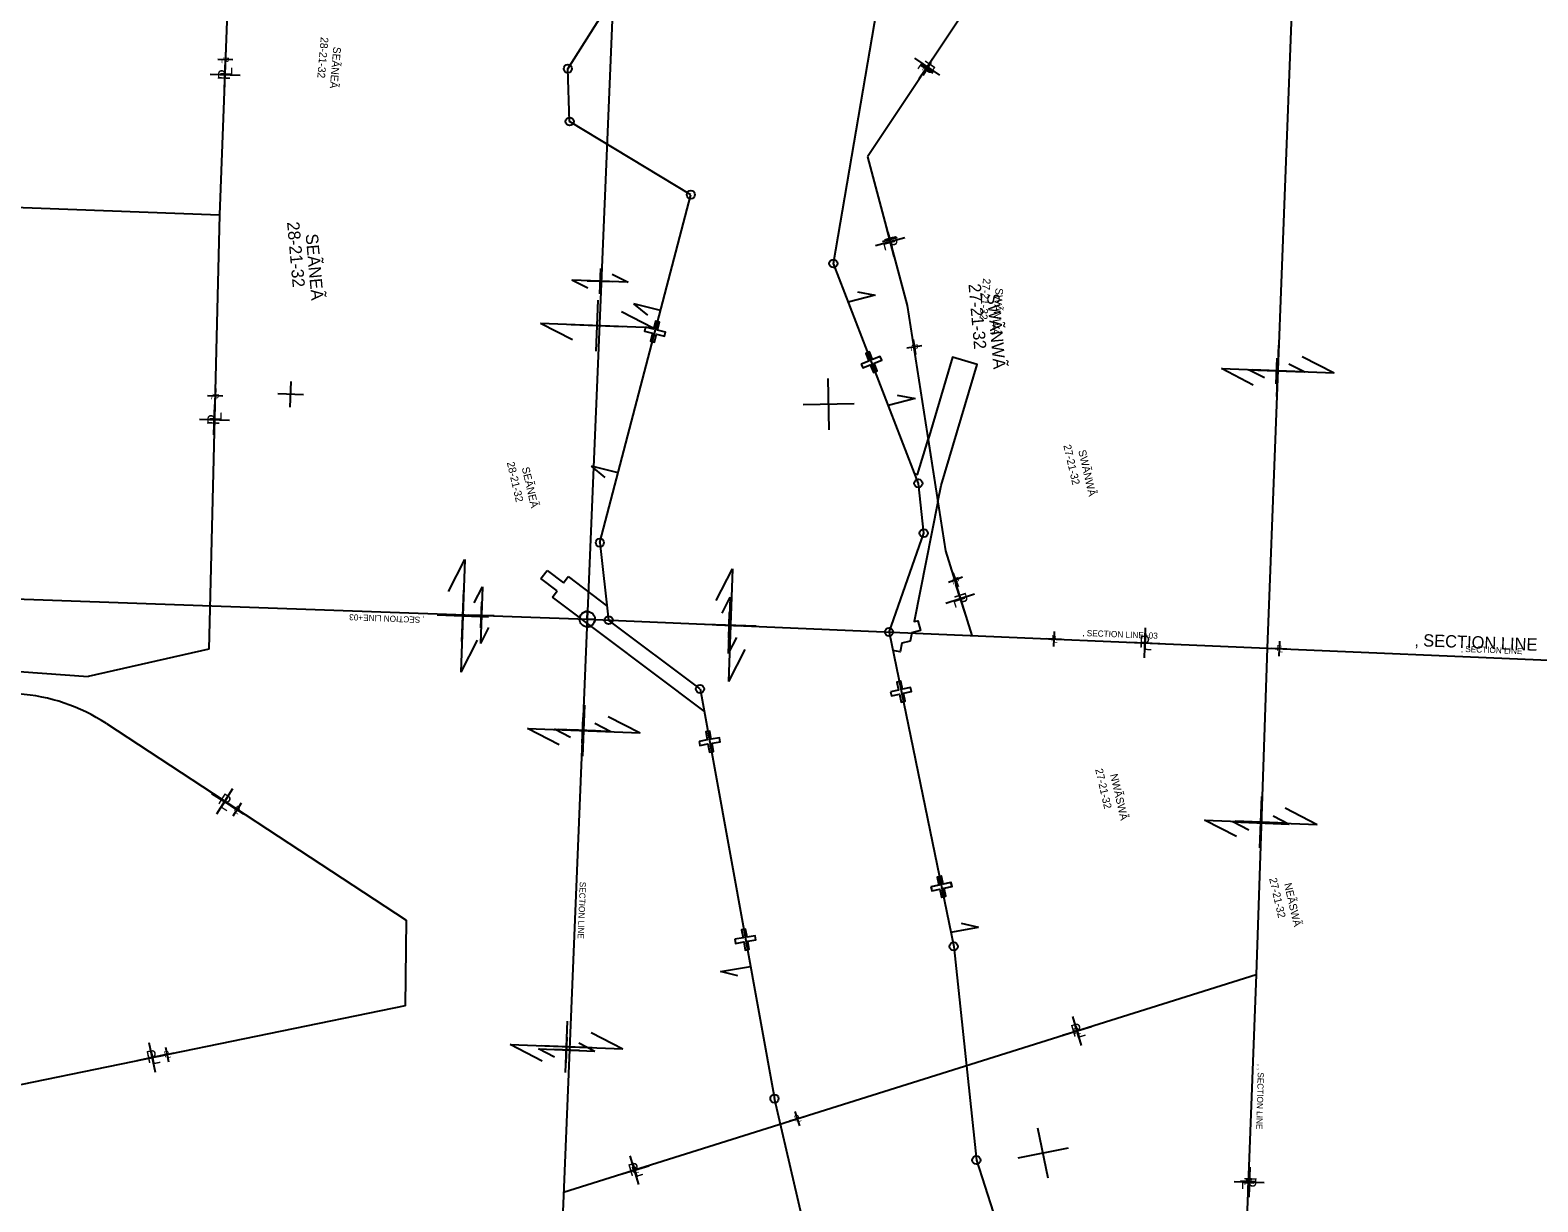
# Model space of a CAD drawing. Extents: x 2814293 to 2835768, y 121185 to 156337.
# Drawn here: x 2819450 to 2822390, y 127276 to 129561 of the extents above; entities that cross this region are included whole.
import ezdxf

# ---------------------------------------------------------------- set-up
doc = ezdxf.new("R2010")
doc.units = 0
for name, color, linetype in [('Default', 7, 'Continuous'), ('Photo-Retaining wall', 7, 'Continuous'), ('Roadway-Alignment notes', 7, 'Continuous'), ('Roadway-Edge of pavement', 7, 'Continuous'), ('Roadway-Edge of shoulder', 7, 'Continuous'), ('Roadway-Entrances', 7, 'Continuous'), ('Roadway-New rw', 7, 'Continuous'), ('Roadway-Permanent easement', 7, 'Continuous'), ('Roadway-Safety', 7, 'Continuous'), ('Roadway-Walls', 7, 'Continuous'), ('Scratch-2', 7, 'Continuous'), ('Scratch-4', 7, 'Continuous'), ('Scratch-5', 7, 'Continuous'), ('Text-New rw label', 7, 'Continuous'), ('Traffic_Control-Traffic barriers', 7, 'Continuous')]:
    doc.layers.add(name, color=color, linetype=linetype)

msp = doc.modelspace()

# ---------------------------------------------------------------- linework, layer by layer
at = {"layer": 'Default'}
for p, q in [((2819957, 128826.3), (2819959, 128876.2)), ((2821008.3, 128781.6), (2821005.9, 128881.6)), ((2819983, 128850.3), (2819933, 128852.2)), ((2821057.1, 128832.8), (2820957.1, 128830.4)), ((2821435, 127321.8), (2821414.9, 127419.8)), ((2821473.9, 127380.8), (2821376, 127360.8))]:
    msp.add_line(p, q, dxfattribs=at)
at = {"layer": 'Roadway-Edge of pavement'}
for p, q in [((2820562, 129096.8), (2820560.1, 129046.8)), ((2820616, 129069.7), (2820506.1, 129073.9)), ((2820537.2, 129057.9), (2820506.1, 129073.9)), ((2820536.1, 129072.7), (2820586.1, 129070.8)), ((2820561.1, 129071.8), (2820561.1, 129071.8)), ((2820584.9, 129085.7), (2820616, 129069.7)), ((2821880, 128871.8), (2821881.9, 128921.8)), ((2821826, 128898.9), (2821935.9, 128894.6)), ((2821857.1, 128882.9), (2821826, 128898.9)), ((2821905.9, 128895.8), (2821856, 128897.7)), ((2821881, 128896.8), (2821881, 128896.8)), ((2821904.8, 128910.6), (2821935.9, 128894.6)), ((2820315.7, 128444.1), (2820331.6, 128475.2)), ((2820331.6, 128475.2), (2820327.7, 128365.3)), ((2820799.1, 128424.2), (2820815, 128455.3)), ((2820815, 128455.3), (2820811.1, 128345.4)), ((2820304.7, 128421.2), (2820354.6, 128419.4)), ((2820328.8, 128395.3), (2820330.5, 128445.3)), ((2820329.6, 128420.3), (2820329.6, 128420.3)), ((2820812.1, 128375.4), (2820813.9, 128425.4)), ((2820343.6, 128396.5), (2820327.7, 128365.3)), ((2820788, 128401.3), (2820838, 128399.5)), ((2820813, 128400.4), (2820813, 128400.4)), ((2820827, 128376.6), (2820811.1, 128345.4)), ((2820526.3, 128170.8), (2820528.2, 128220.7)), ((2820472.3, 128197.9), (2820582.2, 128193.6)), ((2820503.4, 128181.9), (2820472.3, 128197.9)), ((2820552.2, 128194.8), (2820502.3, 128196.7)), ((2820527.3, 128195.8), (2820527.3, 128195.8)), ((2820551.1, 128209.6), (2820582.2, 128193.6)), ((2821849.3, 127989.7), (2821851.3, 128039.7)), ((2821795.3, 128016.8), (2821905.3, 128012.5)), ((2821826.5, 128000.8), (2821795.3, 128016.8)), ((2821875.3, 128013.7), (2821825.3, 128015.6)), ((2821850.3, 128014.7), (2821850.3, 128014.7)), ((2821874.1, 128028.5), (2821905.3, 128012.5)), ((2820495.3, 127546.9), (2820497.2, 127596.9)), ((2820441.3, 127574), (2820551.2, 127569.8)), ((2820472.4, 127558), (2820441.3, 127574)), ((2820521.2, 127570.9), (2820471.2, 127572.9)), ((2820496.2, 127571.9), (2820496.2, 127571.9)), ((2820520.1, 127585.8), (2820551.2, 127569.8)), ((2821425, 127370.8), (2821425, 127370.8))]:
    msp.add_line(p, q, dxfattribs=at)
at = {"layer": 'Roadway-Edge of shoulder'}
for p, q in [((2821223.8, 129473.8), (2821175, 129506.9)), ((2821216, 129514.7), (2821182.8, 129466)), ((2819828.8, 129445.2), (2819830.9, 129504.1)), ((2819800.4, 129475.7), (2819859.3, 129473.6)), ((2821155.4, 129156), (2821098.4, 129141)), ((2821119.4, 129177), (2821134.4, 129120)), ((2819808, 128772.2), (2819810.1, 128831.1)), ((2819779.6, 128802.7), (2819838.5, 128800.6)), ((2821254.5, 128480.2), (2821272.4, 128424.1)), ((2821291.5, 128461.1), (2821235.4, 128443.1)), ((2821624.5, 128395.5), (2821622.2, 128336.7)), ((2821593.9, 128367.3), (2821652.8, 128365)), ((2819803.5, 128072.6), (2819853.4, 128041.2)), ((2819844.2, 128081.8), (2819812.8, 128032)), ((2821482.9, 127637.5), (2821499.7, 127581.1)), ((2821463.1, 127600.9), (2821519.5, 127617.7)), ((2819681.4, 127586.5), (2819693.4, 127528.8)), ((2819658.6, 127551.6), (2819716.3, 127563.7)), ((2820619.5, 127365.9), (2820636.3, 127309.4)), ((2820599.6, 127329.2), (2820656.1, 127346.1)), ((2821828.4, 127343.5), (2821826.3, 127284.7)), ((2821856.8, 127313), (2821797.9, 127315.1))]:
    msp.add_line(p, q, dxfattribs=at)
at = {"layer": 'Roadway-Entrances'}
for p, q in [((2820645.7, 131042.3), (2820536.2, 128412.4)), ((2821962.5, 130985.5), (2821862.4, 128356.1)), ((2821097.5, 129044.7), (2821045.4, 129030.7)), ((2821063, 129050.8), (2821097.5, 129044.7)), ((2820679.2, 129014.7), (2820627, 129027.7)), ((2820654.2, 129005.7), (2820627, 129027.7)), ((2821044.4, 129030.5), (2821044.4, 129030.5)), ((2821175.5, 128843), (2821123.4, 128829.1)), ((2821141, 128849.1), (2821175.5, 128843)), ((2820596.4, 128698.2), (2820544.2, 128711.2)), ((2820571.4, 128689.1), (2820544.2, 128711.2)), ((2817887.6, 128506.6), (2820536.2, 128412.4)), ((2820536.2, 128412.4), (2820428.2, 125785.8)), ((2820536.2, 128412.4), (2823193.2, 128299.4)), ((2821862.4, 128356.1), (2821840.7, 127719.4)), ((2821245.2, 127802.1), (2821299.5, 127811.5)), ((2821265.5, 127819.6), (2821299.5, 127811.5)), ((2820796.1, 127725.1), (2820854.5, 127735.2)), ((2820830.1, 127716.9), (2820796.1, 127725.1)), ((2821840.7, 127719.4), (2821815.2, 127038.4))]:
    msp.add_line(p, q, dxfattribs=at)
at = {"layer": 'Roadway-New rw'}
for p, q in [((2820498.4, 129486.1), (2820693.7, 129795.4)), ((2821016.2, 129106.2), (2821100.8, 129600.8)), ((2820501.8, 129383.2), (2820498.4, 129486.1)), ((2820738.2, 129240.4), (2820501.8, 129383.2)), ((2820560.8, 128561.8), (2820738.2, 129240.4)), ((2821182.1, 128677.3), (2821016.2, 129106.2)), ((2821192.5, 128580.3), (2821182.1, 128677.3)), ((2821124.9, 128387.4), (2821192.5, 128580.3)), ((2820560.8, 128561.8), (2820577.9, 128410.6)), ((2820756.2, 128276.3), (2820577.9, 128410.6)), ((2821124.9, 128387.4), (2821251, 127774.1)), ((2820756.2, 128276.3), (2820901.3, 127477.3)), ((2821251, 127774.1), (2821295.1, 127357.3))]:
    msp.add_line(p, q, dxfattribs=at)
for points in [[(2820650.1, 128981.9), (2820648.1, 128974.2), (2820663.6, 128970.2), (2820659.7, 128954.7), (2820667.4, 128952.7), (2820671.4, 128968.2), (2820686.9, 128964.3), (2820688.9, 128972), (2820673.4, 128976), (2820677.3, 128991.5), (2820669.6, 128993.5), (2820665.6, 128978), (2820650.1, 128981.9)], [(2821070.5, 128910.1), (2821073.5, 128902.6), (2821088.3, 128908.5), (2821094.2, 128893.7), (2821101.7, 128896.6), (2821095.8, 128911.5), (2821110.7, 128917.4), (2821107.7, 128924.8), (2821092.8, 128918.9), (2821086.9, 128933.8), (2821079.5, 128930.8), (2821085.4, 128916), (2821070.5, 128910.1)], [(2821127.7, 128270.7), (2821129.3, 128262.9), (2821145, 128266.2), (2821148.3, 128250.5), (2821156.1, 128252.2), (2821152.8, 128267.8), (2821168.5, 128271.1), (2821166.8, 128278.9), (2821151.2, 128275.7), (2821147.9, 128291.3), (2821140.1, 128289.7), (2821143.4, 128274), (2821127.7, 128270.7)], [(2820754.6, 128174.1), (2820755.9, 128166.2), (2820771.7, 128169), (2820774.5, 128153.2), (2820782.4, 128154.6), (2820779.6, 128170.4), (2820795.3, 128173.1), (2820793.9, 128181), (2820778.2, 128178.2), (2820775.4, 128194), (2820767.5, 128192.6), (2820770.3, 128176.8), (2820754.6, 128174.1)], [(2821206.5, 127890.4), (2821208.1, 127882.6), (2821223.8, 127885.9), (2821227.1, 127870.2), (2821234.9, 127871.9), (2821231.6, 127887.5), (2821247.3, 127890.8), (2821245.6, 127898.7), (2821230, 127895.4), (2821226.7, 127911), (2821218.9, 127909.4), (2821222.1, 127893.7), (2821206.5, 127890.4)], [(2821206.9, 127890.4), (2821208.6, 127882.6), (2821224.2, 127885.9), (2821227.5, 127870.2), (2821235.3, 127871.9), (2821232.1, 127887.5), (2821247.7, 127890.8), (2821246.1, 127898.7), (2821230.4, 127895.4), (2821227.1, 127911), (2821219.3, 127909.4), (2821222.6, 127893.7), (2821206.9, 127890.4)], [(2820824.2, 127788), (2820825.6, 127780.1), (2820841.3, 127782.9), (2820844.1, 127767.1), (2820852, 127768.5), (2820849.2, 127784.2), (2820865, 127787), (2820863.6, 127794.8), (2820847.9, 127792.1), (2820845.1, 127807.9), (2820837.2, 127806.5), (2820840, 127790.7), (2820824.2, 127788)]]:
    msp.add_lwpolyline(points, close=True, dxfattribs=at)
for points in [[(2821246.4, 125990.7), (2820901.3, 127477.3)], [(2821295.1, 127357.3), (2821490.4, 126748.5)]]:
    msp.add_lwpolyline(points, dxfattribs=at)
at = {"layer": 'Roadway-Permanent easement'}
for p, q in [((2820445.7, 128491.5), (2820457.7, 128507.5)), ((2820489.6, 128483.4), (2820498.7, 128495.4)), ((2820498.7, 128495.4), (2820574.8, 128438.1)), ((2820468.6, 128455.5), (2820477.6, 128467.5)), ((2820764.1, 128232.9), (2820468.6, 128455.5))]:
    msp.add_line(p, q, dxfattribs=at)
msp.add_lwpolyline([(2821219.9, 128641.1), (2821226.3, 128673.3), (2821296.8, 128909.4), (2821248.9, 128923.7), (2821200.9, 128763.1)], close=True, dxfattribs=at)
for points in [[(2821174.7, 128696.4), (2821180.6, 128694.9), (2821200.9, 128763.1), (2821219.9, 128641.1), (2821173.7, 128407.6), (2821181, 128409.5), (2821186, 128390.1), (2821169.4, 128385.9), (2821166.2, 128369.6), (2821150.1, 128365.5), (2821146.8, 128348.7), (2821132.3, 128351.6)], [(2820457.7, 128507.5), (2820489.6, 128483.4)], [(2820477.6, 128467.5), (2820445.7, 128491.5)]]:
    msp.add_lwpolyline(points, dxfattribs=at)
at = {"layer": 'Roadway-Walls'}
for p, q in [((2819830.7, 129518.4), (2819829.7, 129489)), ((2819844.9, 129503.2), (2819815.5, 129504.2)), ((2821211.1, 129477.7), (2821186.2, 129493.4)), ((2821206.5, 129498), (2821190.8, 129473.1)), ((2821140.5, 129156.8), (2821112.1, 129148.8)), ((2821122.3, 129167), (2821130.3, 129138.6)), ((2821171.9, 128958.1), (2821176.4, 128929)), ((2821188.7, 128945.8), (2821159.6, 128941.3)), ((2819811, 128862.5), (2819809.9, 128833.1)), ((2819825.2, 128847.3), (2819795.7, 128848.3)), ((2821268.4, 128494.2), (2821240.9, 128483.7)), ((2821249.4, 128502.7), (2821259.9, 128475.2)), ((2821431.6, 128374.5), (2821461, 128373.3)), ((2821446.9, 128388.6), (2821445.7, 128359.2)), ((2821886.4, 128369.8), (2821885.2, 128340.4)), ((2821871.1, 128355.7), (2821900.5, 128354.5)), ((2819840.6, 128048.7), (2819865.5, 128033)), ((2819860.9, 128053.3), (2819845.2, 128028.4)), ((2821476.4, 127604.7), (2821504.6, 127613.1)), ((2821486.3, 127623), (2821494.8, 127594.8)), ((2819701.9, 127560.2), (2819730.7, 127566.2)), ((2819713.3, 127577.6), (2819719.3, 127548.8)), ((2820941.4, 127452.3), (2820949.9, 127424.1)), ((2820931.5, 127434), (2820959.8, 127442.5)), ((2820614.4, 127333.7), (2820642.7, 127342.1)), ((2820624.4, 127352), (2820632.8, 127323.8)), ((2821840, 127314.8), (2821810.6, 127315.9)), ((2821825.8, 127330.1), (2821824.8, 127300.6))]:
    msp.add_line(p, q, dxfattribs=at)
at = {"layer": 'Scratch-2'}
for p, q in [((2820557, 129035), (2820553, 128935.1)), ((2820602.7, 129012.8), (2820664.9, 128980.7)), ((2820664.9, 128980.7), (2820445.1, 128989.4)), ((2820507.3, 128957.4), (2820445.1, 128989.4)), ((2820505, 128987.1), (2820604.9, 128983.1)), ((2820555, 128985.1), (2820555, 128985.1)), ((2821881.1, 128847), (2821885, 128947)), ((2821930.7, 128924.7), (2821992.9, 128892.7)), ((2821773.1, 128901.2), (2821992.9, 128892.7)), ((2821835.3, 128869.2), (2821773.1, 128901.2)), ((2821933, 128895), (2821833.1, 128898.9)), ((2821883, 128897), (2821883, 128897)), ((2820265.5, 128466.7), (2820297.3, 128529)), ((2820297.3, 128529), (2820289.6, 128309.1)), ((2820787.9, 128448.6), (2820819.7, 128510.9)), ((2820819.7, 128510.9), (2820812, 128291)), ((2820291.7, 128369.1), (2820295.2, 128469)), ((2820814.1, 128351), (2820817.6, 128450.9)), ((2820243.5, 128420.8), (2820343.4, 128417.3)), ((2820293.5, 128419.1), (2820293.5, 128419.1)), ((2820765.9, 128402.7), (2820865.8, 128399.2)), ((2820815.9, 128401), (2820815.9, 128401)), ((2820321.4, 128371.5), (2820289.6, 128309.1)), ((2820843.8, 128353.4), (2820812, 128291)), ((2820527.4, 128145.1), (2820531.2, 128245)), ((2820577, 128222.8), (2820639.2, 128190.8)), ((2820419.4, 128199.3), (2820639.2, 128190.8)), ((2820481.6, 128167.3), (2820419.4, 128199.3)), ((2820579.3, 128193.1), (2820479.3, 128197)), ((2820529.3, 128195.1), (2820529.3, 128195.1)), ((2821848.1, 127966.3), (2821851.9, 128066.3)), ((2821897.7, 128044.1), (2821959.9, 128012)), ((2821740.1, 128020.6), (2821959.9, 128012)), ((2821802.3, 127988.5), (2821740.1, 128020.6)), ((2821900, 128014.4), (2821800, 128018.2)), ((2821850, 128016.3), (2821850, 128016.3)), ((2820494, 127528.3), (2820497.9, 127628.2)), ((2820543.6, 127606), (2820605.8, 127574)), ((2820386, 127582.5), (2820605.8, 127574)), ((2820448.3, 127550.5), (2820386, 127582.5)), ((2820545.9, 127576.3), (2820446, 127580.2)), ((2820495.9, 127578.2), (2820495.9, 127578.2)), ((2821425, 127370.8), (2821425, 127370.8))]:
    msp.add_line(p, q, dxfattribs=at)
at = {"layer": 'Scratch-4'}
for p, q in [((2820536.2, 128412.4), (2820536.7, 128427.4)), ((2820521.2, 128412.9), (2820536.2, 128412.4)), ((2820536.2, 128412.4), (2820535.7, 128397.4)), ((2820551.2, 128411.9), (2820536.2, 128412.4))]:
    msp.add_line(p, q, dxfattribs=at)
msp.add_circle((2820536.2, 128412.4), 15, dxfattribs=at)
for start, end in [(88.1, 178.1), (268.1, 358.1)]:
    msp.add_arc((2820536.2, 128412.4), 15, start, end, dxfattribs=at)
at = {"layer": 'Text-New rw label'}
for centre in [(2820498.4, 129486.1), (2820501.8, 129383.2), (2820738.2, 129240.4), (2821016.2, 129106.2), (2821182.1, 128677.3), (2820560.8, 128561.8), (2821192.5, 128580.3), (2820577.9, 128410.6), (2821124.9, 128387.4), (2820756.2, 128276.3), (2821251, 127774.1), (2820901.3, 127477.3), (2821295.1, 127357.3)]:
    msp.add_circle(centre, 8, dxfattribs=at)
at = {"layer": 'Traffic_Control-Traffic barriers'}
for p, q in [((2821312.8, 129660.4), (2821082.9, 129314.5)), ((2821082.9, 129314.5), (2821160.3, 129024.5)), ((2818869.8, 129236.6), (2819819.2, 129201.2)), ((2821160.3, 129024.5), (2821234.8, 128545.6)), ((2821234.8, 128545.6), (2821286, 128380.5)), ((2818738, 128359.7), (2819562.7, 128300.6)), ((2819798.3, 128353.8), (2819562.7, 128300.6)), ((2819598.3, 128208.8), (2820183.1, 127825.5)), ((2820183.1, 127825.5), (2820180.8, 127658.5)), ((2820490.2, 127294.7), (2821840.7, 127719.4)), ((2820180.8, 127658.5), (2819212.7, 127459.2))]:
    msp.add_line(p, q, dxfattribs=at)
msp.add_lwpolyline([(2819839.7, 129750.8), (2819819.2, 129201.2), (2819798.3, 128353.8)], dxfattribs=at)
msp.add_arc((2819401.1, 127908), 359.7, 56.7576, 85.901, dxfattribs=at)
msp.add_open_spline([(2818787.1, 128593.2), (2818789.2, 128610.4), (2818801, 128699.9), (2818831.4, 128865.4), (2818867.8, 129199.8), (2818876.3, 129324.7), (2818898.3, 129421.6), (2818849.4, 129639.4), (2818839.1, 129653.4), (2818819.7, 129750.6), (2818972.3, 129919), (2819007.2, 129963.4), (2819027.6, 130013.6), (2819053.1, 130078.1), (2819201.8, 130156.7), (2819261.5, 130171.2), (2819306.5, 130181.7), (2819476.3, 130228.2), (2819611.7, 130321.2), (2819826.5, 130470.1), (2819939.3, 130532.3), (2820143.5, 130786.8), (2820228.9, 130908.5), (2820347.4, 131066), (2820389.8, 131123.7), (2820379.9, 131244.4), (2820364.1, 131374.7), (2820344, 131475.4), (2820328.8, 131545)], degree=3, dxfattribs=at)

# ---------------------------------------------------------------- texts
at = {"layer": 'Photo-Retaining wall'}
for s, rotation, p in [('28-21-32', 265.038, (2820016.6, 129548.3)), ('SEÃNEÃ', 265.038, (2820041.1, 129529.5)), ('27-21-32', 265.038, (2821308.3, 129077.6)), ('SWÃNWÃ', 265.038, (2821332.8, 129058.9)), ('27-21-32', 283.038, (2821464.7, 128751.3)), ('SWÃNWÃ', 283.038, (2821493.8, 128741)), ('28-21-32', 283.038, (2820379.3, 128717.8)), ('SEÃNEÃ', 283.038, (2820408.4, 128707.5)), ('27-21-32', 283.038, (2821526.8, 128119.3)), ('NWÃSWÃ', 283.038, (2821555.9, 128109)), ('27-21-32', 283.038, (2821866.1, 127906.4)), ('NEÃSWÃ', 283.038, (2821895.1, 127896.1))]:
    msp.add_text(s, height=15, rotation=rotation, dxfattribs=at).set_placement(p)
at = {"layer": 'Roadway-Alignment notes'}
for s, p in [('28-21-32', (2819950.6, 129186.8)), ('SEÃNEÃ', (2819986.8, 129163.3)), ('27-21-32', (2821279.7, 129066)), ('SWÃNWÃ', (2821315.6, 129046.7))]:
    msp.add_text(s, height=24, rotation=275.0693, dxfattribs=at).set_placement(p)
at = {"layer": 'Roadway-Edge of shoulder'}
for s, rotation, p in [('P', 87.9775, (2819839.1, 129463.6)), ('L', 87.9775, (2819843.7, 129471.5)), ('L', 235.7804, (2821189.4, 129500.4)), ('P', 235.7804, (2821197.4, 129504.6)), ('P', 284.7804, (2821114.9, 129156.4)), ('L', 284.7804, (2821112.8, 129147.5)), ('P', 87.9775, (2819818.3, 128790.7)), ('L', 87.9775, (2819822.9, 128798.5)), ('L', 287.7804, (2821249.4, 128450.4)), ('P', 287.7804, (2821251, 128459.4)), ('P', 357.7804, (2821612.3, 128356.9)), ('L', 357.7804, (2821620.1, 128352.3)), ('P', 327.7804, (2819814.3, 128054.4)), ('L', 327.7804, (2819818.8, 128046.5)), ('P', 16.6261, (2821483.8, 127597)), ('L', 16.6261, (2821492.7, 127595.2)), ('P', 11.7804, (2819678.9, 127546)), ('L', 11.7804, (2819687.6, 127543.5)), ('P', 16.6261, (2820620.4, 127325.3)), ('L', 16.6261, (2820629.3, 127323.5)), ('L', 267.9775, (2821813.5, 127317.3)), ('P', 267.9775, (2821818.1, 127325.1))]:
    msp.add_text(s, height=23.6, rotation=rotation, dxfattribs=at).set_placement(p)
at = {"layer": 'Roadway-Safety'}
for s, rotation, p in [('‚ SECTION LINE+03', 177.7804, (2820218.8, 128416.7)), ('‚ SECTION LINE+03', 357.7804, (2821502.2, 128379.7)), ('‚ SECTION LINE', 357.7804, (2822240.5, 128348.7)), ('SECTION LINE', 267.8429, (2820521.7, 127900.4)), ('‚ ‚ SECTION LINE', 268.4541, (2821844.4, 127544.7))]:
    msp.add_text(s, height=12, rotation=rotation, dxfattribs=at).set_placement(p)
at = {"layer": 'Roadway-Walls'}
for s, rotation, p in [('P', 267.9775, (2819825.6, 129509.2)), ('L', 267.9775, (2819823.3, 129505.3)), ('L', 237.7804, (2821193.5, 129490.4)), ('P', 237.7804, (2821197.5, 129492.6)), ('L', 285.7804, (2821119.2, 129152.2)), ('P', 285.7804, (2821120.2, 129156.7)), ('P', 278.7804, (2821168.6, 128948.1)), ('L', 278.7804, (2821167.1, 128943.8)), ('L', 267.9775, (2819803.5, 128849.4)), ('P', 267.9775, (2819805.8, 128853.3)), ('L', 290.892, (2821247.6, 128487.7)), ('P', 290.892, (2821248.2, 128492.2)), ('P', 357.7804, (2821440.8, 128369.3)), ('L', 357.7804, (2821444.7, 128367)), ('P', 357.7804, (2821880.3, 128350.5)), ('L', 357.7804, (2821884.2, 128348.2)), ('P', 327.7804, (2819846, 128039.6)), ('L', 327.7804, (2819848.2, 128035.6)), ('P', 16.6261, (2821486.8, 127602.7)), ('L', 16.6261, (2821491.2, 127601.8)), ('P', 11.7804, (2819712, 127557.4)), ('L', 11.7804, (2819716.4, 127556.1)), ('P', 16.6261, (2820941.9, 127432.1)), ('L', 16.6261, (2820946.3, 127431.2)), ('P', 16.6261, (2820624.8, 127331.8)), ('L', 16.6261, (2820629.3, 127330.9)), ('L', 267.9775, (2821818.4, 127316.9)), ('P', 267.9775, (2821820.7, 127320.9))]:
    msp.add_text(s, height=11.8, rotation=rotation, dxfattribs=at).set_placement(p)
at = {"layer": 'Scratch-5'}
msp.add_text('‚ SECTION LINE', height=24, rotation=357.7804, dxfattribs=at).set_placement((2822150.2, 128360))

doc.saveas('drawing.dxf')
